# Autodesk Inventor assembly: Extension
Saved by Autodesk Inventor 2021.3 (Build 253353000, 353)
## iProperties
Created: 2022-04
Part Number: Extension
Document SubType Name: Assembly
Designer: Administrator
Title: Extension v24
Author: Administrator
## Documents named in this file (2)
- c:\worker\convert-fusion-r02\tmp\job-1\57\output\files\f9e42cba-e390-44b0-9630-f24d5638462a\Extension v24.iam
- c:\worker\convert-fusion-r02\tmp\job-1\57\output\files\f9e42cba-e390-44b0-9630-f24d5638462a\Component1_3.ipt
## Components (1 placed, 1 different names)
1. Component1:1
